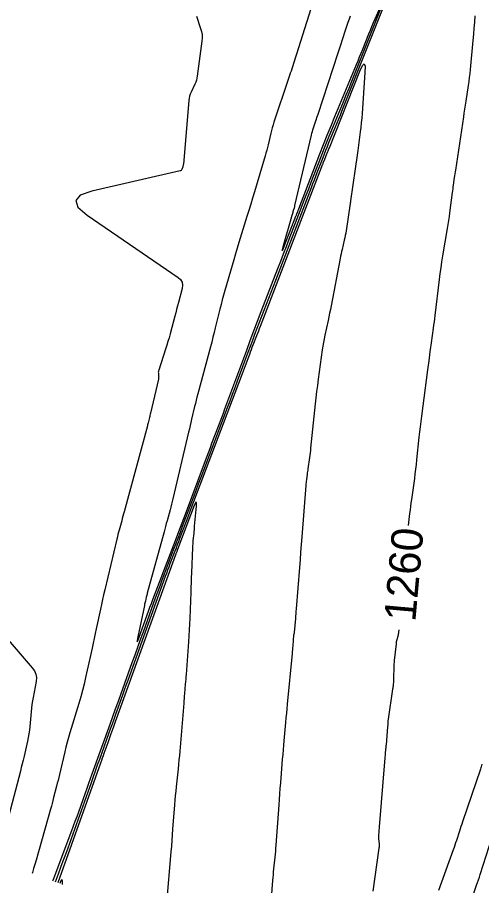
# Model space of a CAD drawing. Extents: x 658976 to 668721, y 639543 to 647196.
# Drawn here: x 661603.2 to 661691.9, y 641247 to 641412.7 of the extents above; entities that cross this region are included whole.
import ezdxf

# ---------------------------------------------------------------- set-up
doc = ezdxf.new("R2010")
doc.units = 0
for name, color, linetype in [('Ex_Contour Labels', 7, 'Continuous'), ('Ex_Major Contours', 7, 'Continuous'), ('Ex_Minor Contours', 7, 'Continuous')]:
    doc.layers.add(name, color=color, linetype=linetype)

msp = doc.modelspace()

# ---------------------------------------------------------------- linework, layer by layer
at = {"layer": 'Ex_Major Contours'}
for points in [[(661609.98, 641247.86), (661610.05, 641248.02), (661613.61, 641257.48), (661613.95, 641258.38), (661614.28, 641259.28), (661614.61, 641260.18), (661614.93, 641261.08), (661616.23, 641264.69), (661616.55, 641265.6), (661616.87, 641266.5), (661617.2, 641267.4), (661617.52, 641268.3), (661620.92, 641277.78), (661621.45, 641279.25), (661621.98, 641280.72), (661622.51, 641282.19), (661623.04, 641283.66), (661625.15, 641289.55), (661625.68, 641291.02), (661626.21, 641292.48), (661626.74, 641293.95), (661627.27, 641295.41), (661629.62, 641301.92), (661630.03, 641303.07), (661630.46, 641304.21), (661630.88, 641305.35), (661631.31, 641306.48), (661633.05, 641311.03), (661633.48, 641312.16), (661633.92, 641313.3), (661634.35, 641314.44), (661634.77, 641315.58), (661636.84, 641321.07), (661637.33, 641322.37), (661637.82, 641323.66), (661638.31, 641324.95), (661638.8, 641326.25), (661643.35, 641338.2), (661643.84, 641339.49), (661644.32, 641340.77), (661644.81, 641342.06), (661645.28, 641343.34), (661647.3, 641348.77), (661647.72, 641349.92), (661648.15, 641351.07), (661648.59, 641352.21), (661649.03, 641353.36), (661650.79, 641357.93), (661651.24, 641359.07), (661651.68, 641360.21), (661652.12, 641361.36), (661652.56, 641362.5), (661659.39, 641380.24), (661659.66, 641380.95), (661659.94, 641381.66), (661660.21, 641382.38), (661660.49, 641383.09), (661661.58, 641385.94), (661661.86, 641386.65), (661662.14, 641387.36), (661662.43, 641388.07), (661662.72, 641388.78), (661663.98, 641391.82), (661664.29, 641392.56), (661664.6, 641393.31), (661664.9, 641394.05), (661665.2, 641394.8), (661675.24, 641419.95)], [(661637.4, 641412.92), (661638.21, 641410.57), (661638.38, 641409.98), (661638.48, 641409.38), (661638.5, 641408.78), (661638.46, 641408.17), (661637.57, 641401.49), (661637.5, 641401.09), (661637.4, 641400.69), (661637.27, 641400.3), (661637.11, 641399.92), (661636.4, 641398.42), (661636.24, 641398.04), (661636.11, 641397.65), (661636.03, 641397.25), (661635.97, 641396.84), (661634.91, 641384.64), (661634.9, 641384.52), (661634.87, 641384.39), (661634.84, 641384.27), (661634.8, 641384.15), (661634.62, 641383.67), (661634.56, 641383.56), (661634.49, 641383.48), (661634.39, 641383.42), (661634.28, 641383.38), (661617.42, 641379.53), (661615.23, 641378.75), (661614.35, 641377.73), (661614.79, 641376.45), (661616.55, 641374.92), (661633.9, 641363.05), (661634.38, 641362.63), (661634.66, 641362.14), (661634.77, 641361.58), (661634.68, 641360.95), (661633.98, 641358.29), (661633.8, 641357.62), (661633.62, 641356.96), (661633.45, 641356.3), (661633.27, 641355.63), (661632.37, 641352.28), (661632.17, 641351.55), (661631.96, 641350.83), (661631.74, 641350.11), (661631.51, 641349.39), (661630.2, 641345.36), (661630.17, 641345.22), (661630.14, 641345.09), (661630.13, 641344.94), (661630.14, 641344.8), (661630.19, 641344.23), (661630.2, 641344.08), (661630.19, 641343.94), (661630.18, 641343.8), (661630.15, 641343.66), (661628.62, 641337.14), (661628.57, 641336.94), (661628.52, 641336.73), (661628.48, 641336.53), (661628.43, 641336.33), (661628.24, 641335.53), (661628.19, 641335.33), (661628.14, 641335.13), (661628.09, 641334.93), (661628.04, 641334.73), (661623.61, 641318.34), (661623.49, 641317.9), (661623.37, 641317.46), (661623.25, 641317.02), (661623.13, 641316.59), (661622.66, 641314.84), (661622.54, 641314.4), (661622.42, 641313.96), (661622.31, 641313.52), (661622.21, 641313.08), (661619.89, 641303.4), (661619.67, 641302.48), (661619.46, 641301.56), (661619.26, 641300.63), (661619.07, 641299.71), (661618.29, 641296.01), (661618.1, 641295.09), (661617.9, 641294.16), (661617.7, 641293.24), (661617.5, 641292.32), (661616.25, 641286.69), (661615.96, 641285.44), (661615.65, 641284.21), (661615.31, 641282.98), (661614.95, 641281.75), (661613.23, 641276.12), (661612.96, 641275.22), (661612.71, 641274.33), (661612.48, 641273.42), (661612.26, 641272.52), (661611.24, 641268.16), (661611.11, 641267.61), (661610.98, 641267.06), (661610.84, 641266.51), (661610.7, 641265.96), (661610.14, 641263.77), (661610, 641263.22), (661609.85, 641262.67), (661609.71, 641262.13), (661609.55, 641261.58), (661606.78, 641251.8), (661606.55, 641251.03), (661606.32, 641250.26), (661606.09, 641249.49), (661606.03, 641249.3)], [(661690.55, 641412.98), (661690.48, 641411.8), (661690.39, 641410.62), (661690.3, 641409.45), (661690.2, 641408.27), (661689.68, 641402.74), (661689.6, 641401.98), (661689.51, 641401.22), (661689.41, 641400.47), (661689.3, 641399.71), (661688.84, 641396.7), (661688.72, 641395.94), (661688.61, 641395.19), (661688.49, 641394.43), (661688.38, 641393.68), (661686.85, 641383.53), (661686.8, 641383.18), (661686.75, 641382.82), (661686.69, 641382.46), (661686.64, 641382.1), (661686.44, 641380.67), (661686.39, 641380.32), (661686.35, 641379.96), (661686.3, 641379.6), (661686.25, 641379.24), (661685.74, 641375.41), (661685.64, 641374.66), (661685.53, 641373.9), (661685.41, 641373.15), (661685.29, 641372.39), (661684.4, 641367.16), (661684.22, 641366.03), (661684.05, 641364.9), (661683.9, 641363.77), (661683.75, 641362.64), (661682.94, 641355.78), (661682.87, 641355.18), (661682.79, 641354.57), (661682.71, 641353.96), (661682.63, 641353.36), (661682.23, 641350.58), (661682.17, 641350.15), (661682.11, 641349.72), (661682.05, 641349.29), (661681.99, 641348.86), (661681.76, 641347.14), (661681.7, 641346.71), (661681.65, 641346.28), (661681.59, 641345.85), (661681.53, 641345.42), (661680.36, 641336.59), (661680.23, 641335.57), (661680.11, 641334.56), (661680, 641333.55), (661679.89, 641332.54), (661679.45, 641328.23), (661679.36, 641327.34), (661679.25, 641326.45), (661679.14, 641325.56), (661679.02, 641324.67), (661678.46, 641320.68), (661678.37, 641320.01), (661678.28, 641319.34), (661678.2, 641318.67), (661678.12, 641318), (661677.85, 641315.73)], [(661676.06, 641295.81), (661676.02, 641295.34), (661675.99, 641295.15), (661675.96, 641294.96), (661675.93, 641294.78), (661675.88, 641294.59), (661675.67, 641293.86), (661675.62, 641293.68), (661675.58, 641293.49), (661675.55, 641293.31), (661675.53, 641293.12), (661675.19, 641289.95), (661675.16, 641289.59), (661675.13, 641289.23), (661675.11, 641288.87), (661675.1, 641288.52), (661675.07, 641286.74), (661675.07, 641286.55), (661675.06, 641286.36), (661675.05, 641286.17), (661675.03, 641285.98), (661674.96, 641285.22), (661674.95, 641285.03), (661674.92, 641284.84), (661674.9, 641284.65), (661674.87, 641284.46), (661674.01, 641278.71), (661674, 641278.6), (661673.99, 641278.48), (661673.98, 641278.36), (661673.97, 641278.24), (661673.95, 641277.77), (661673.94, 641277.66), (661673.93, 641277.54), (661673.92, 641277.42), (661673.91, 641277.3), (661673.62, 641273.84), (661673.6, 641273.63), (661673.58, 641273.43), (661673.56, 641273.22), (661673.54, 641273.02), (661673.46, 641272.2), (661673.44, 641271.99), (661673.42, 641271.79), (661673.4, 641271.58), (661673.38, 641271.37), (661672.33, 641258.16), (661672.32, 641258.09), (661672.31, 641258.02), (661672.31, 641257.95), (661672.3, 641257.88), (661672.27, 641257.6), (661672.27, 641257.54), (661672.26, 641257.47), (661672.26, 641257.4), (661672.25, 641257.33), (661672.2, 641256.53), (661672.19, 641256.38), (661672.19, 641256.22), (661672.19, 641256.06), (661672.2, 641255.91), (661672.28, 641254.97), (661672.29, 641254.76), (661672.29, 641254.55), (661672.28, 641254.34), (661672.25, 641254.14), (661671.08, 641245.9)]]:
    msp.add_lwpolyline(points, dxfattribs=at)
at = {"layer": 'Ex_Minor Contours'}
for points in [[(661660.43, 641418.02), (661656.53, 641405.68), (661656.4, 641405.27), (661656.27, 641404.87), (661656.14, 641404.46), (661656, 641404.05), (661655.47, 641402.43), (661655.33, 641402.02), (661655.2, 641401.62), (661655.07, 641401.21), (661654.93, 641400.81), (661652.22, 641392.7), (661652.05, 641392.17), (661651.9, 641391.63), (661651.75, 641391.1), (661651.62, 641390.56), (661651.11, 641388.39), (661650.98, 641387.85), (661650.84, 641387.31), (661650.69, 641386.77), (661650.53, 641386.23), (661648.5, 641379.4), (661648.14, 641378.21), (661647.78, 641377.03), (661647.41, 641375.84), (661647.05, 641374.65), (661645.51, 641369.71), (661645.17, 641368.62), (661644.84, 641367.53), (661644.52, 641366.44), (661644.21, 641365.35), (661642.84, 641360.56), (661642.59, 641359.67), (661642.35, 641358.78), (661642.11, 641357.88), (661641.89, 641356.99), (661641, 641353.41), (661640.78, 641352.51), (661640.55, 641351.62), (661640.32, 641350.72), (661640.08, 641349.83), (661637.67, 641340.83), (661637.51, 641340.22), (661637.35, 641339.62), (661637.2, 641339.01), (661637.06, 641338.4), (661636.49, 641335.97), (661636.34, 641335.37), (661636.2, 641334.76), (661636.06, 641334.15), (661635.91, 641333.54), (661632.9, 641320.82), (661632.78, 641320.28), (661632.64, 641319.75), (661632.51, 641319.23), (661632.37, 641318.7), (661631.8, 641316.59), (661631.65, 641316.06), (661631.51, 641315.53), (661631.37, 641315), (661631.22, 641314.48), (661628.03, 641302.79), (661627.98, 641302.6), (661627.93, 641302.41), (661627.88, 641302.21), (661627.83, 641302.02), (661627.65, 641301.24), (661627.6, 641301.05), (661627.56, 641300.85), (661627.52, 641300.66), (661627.47, 641300.46), (661626.22, 641294.43), (661626.09, 641293.73), (661626.09, 641293.48), (661626.21, 641293.69), (661626.47, 641294.36), (661628.27, 641299.35), (661628.33, 641299.53), (661628.4, 641299.72), (661628.47, 641299.9), (661628.53, 641300.09), (661628.8, 641300.82), (661628.86, 641301), (661628.93, 641301.19), (661629, 641301.37), (661629.07, 641301.55), (661632.76, 641311.2), (661633.39, 641312.87), (661634.03, 641314.54), (661634.66, 641316.21), (661635.29, 641317.88), (661639.14, 641328.12), (661639.45, 641328.94), (661639.76, 641329.75), (661640.07, 641330.57), (661640.38, 641331.39), (661641.63, 641334.67), (661641.94, 641335.48), (661642.25, 641336.3), (661642.55, 641337.12), (661642.86, 641337.94), (661647.02, 641349.17), (661647.7, 641351.01), (661648.4, 641352.85), (661649.1, 641354.69), (661649.8, 641356.53), (661652.98, 641364.75), (661653.52, 641366.15), (661654.06, 641367.55), (661654.6, 641368.95), (661655.13, 641370.35), (661657.4, 641376.24), (661657.88, 641377.49), (661658.37, 641378.74), (661658.85, 641379.99), (661659.33, 641381.24), (661661.26, 641386.25), (661661.74, 641387.5), (661662.24, 641388.75), (661662.74, 641389.99), (661663.25, 641391.23), (661665.47, 641396.58), (661666.01, 641397.88), (661666.55, 641399.19), (661667.08, 641400.5), (661667.6, 641401.81), (661672.53, 641414.16)], [(661674.17, 641418.45), (661671.48, 641412.35), (661671.17, 641411.63), (661670.86, 641410.91), (661670.56, 641410.18), (661670.26, 641409.45), (661669.1, 641406.53), (661668.8, 641405.8), (661668.51, 641405.07), (661668.21, 641404.34), (661667.91, 641403.61), (661663.78, 641393.69), (661663.05, 641391.91), (661662.33, 641390.13), (661661.62, 641388.35), (661660.93, 641386.56), (661656.89, 641376.05), (661656.84, 641375.93), (661656.8, 641375.82), (661656.75, 641375.7), (661656.71, 641375.58), (661656.53, 641375.12), (661656.48, 641375), (661656.44, 641374.88), (661656.39, 641374.77), (661656.35, 641374.65), (661654.19, 641369.08), (661653.91, 641368.38), (661653.79, 641368.16), (661653.83, 641368.41), (661654.02, 641369.13), (661655.61, 641374.68), (661655.64, 641374.78), (661655.67, 641374.88), (661655.7, 641374.98), (661655.73, 641375.08), (661655.85, 641375.48), (661655.88, 641375.57), (661655.91, 641375.67), (661655.94, 641375.77), (661655.97, 641375.87), (661656.11, 641376.32), (661656.14, 641376.42), (661656.17, 641376.53), (661656.19, 641376.64), (661656.22, 641376.75), (661659.39, 641390.23), (661659.47, 641390.57), (661659.56, 641390.91), (661659.66, 641391.25), (661659.77, 641391.58), (661660.21, 641392.91), (661660.32, 641393.24), (661660.43, 641393.58), (661660.54, 641393.91), (661660.65, 641394.24), (661664.5, 641405.89), (661664.69, 641406.48), (661664.88, 641407.07), (661665.07, 641407.66), (661665.26, 641408.25), (661666.01, 641410.62), (661666.2, 641411.21), (661666.4, 641411.8), (661666.62, 641412.38), (661666.84, 641412.96)], [(661610.47, 641247.68), (661611.07, 641249.25), (661611.53, 641250.49), (661611.99, 641251.73), (661612.44, 641252.97), (661612.89, 641254.21), (661617.34, 641266.66), (661617.74, 641267.78), (661618.14, 641268.89), (661618.54, 641270.01), (661618.95, 641271.13), (661620.69, 641276), (661621.02, 641276.92), (661621.36, 641277.85), (661621.69, 641278.77), (661622.02, 641279.7), (661623.35, 641283.4), (661623.69, 641284.32), (661624.02, 641285.25), (661624.35, 641286.17), (661624.69, 641287.1), (661631.52, 641306.02), (661631.74, 641306.63), (661631.96, 641307.23), (661632.19, 641307.84), (661632.42, 641308.44), (661633.34, 641310.86), (661633.57, 641311.46), (661633.8, 641312.06), (661634.03, 641312.67), (661634.26, 641313.27), (661635.36, 641316.19), (661635.62, 641316.88), (661635.88, 641317.57), (661636.14, 641318.25), (661636.4, 641318.94), (661646.03, 641344.22), (661646.22, 641344.73), (661646.41, 641345.23), (661646.6, 641345.74), (661646.78, 641346.25), (661647.58, 641348.38), (661647.74, 641348.83), (661647.91, 641349.28), (661648.08, 641349.73), (661648.26, 641350.18), (661648.95, 641351.98), (661649.12, 641352.43), (661649.3, 641352.88), (661649.47, 641353.33), (661649.64, 641353.78), (661661.37, 641384.24), (661661.44, 641384.41), (661661.51, 641384.59), (661661.58, 641384.76), (661661.64, 641384.93), (661661.91, 641385.63), (661661.98, 641385.8), (661662.05, 641385.97), (661662.12, 641386.15), (661662.19, 641386.32), (661662.49, 641387.06), (661662.57, 641387.24), (661662.64, 641387.42), (661662.72, 641387.61), (661662.79, 641387.79), (661668.63, 641402.41), (661669.13, 641403.51), (661669.46, 641403.84), (661669.62, 641403.4), (661669.59, 641402.19), (661669.05, 641394.34), (661668.98, 641393.46), (661668.89, 641392.57), (661668.8, 641391.69), (661668.69, 641390.81), (661668.22, 641387.28), (661668.1, 641386.4), (661667.98, 641385.52), (661667.86, 641384.64), (661667.73, 641383.76), (661666.85, 641377.67), (661666.85, 641377.62), (661666.84, 641377.58), (661666.83, 641377.54), (661666.83, 641377.5), (661666.8, 641377.33), (661666.79, 641377.29), (661666.78, 641377.25), (661666.78, 641377.21), (661666.77, 641377.16), (661665.98, 641371.96), (661665.91, 641371.52), (661665.83, 641371.07), (661665.74, 641370.62), (661665.64, 641370.18), (661665.23, 641368.41), (661665.13, 641367.97), (661665.03, 641367.53), (661664.94, 641367.08), (661664.85, 641366.64), (661663.12, 641357.65), (661662.98, 641356.95), (661662.84, 641356.25), (661662.69, 641355.55), (661662.54, 641354.85), (661661.93, 641352.05), (661661.78, 641351.35), (661661.65, 641350.65), (661661.53, 641349.94), (661661.43, 641349.23), (661660.66, 641343.61), (661660.5, 641342.43), (661660.36, 641341.26), (661660.22, 641340.08), (661660.09, 641338.9), (661659.22, 641330.45), (661659.17, 641330.01), (661659.12, 641329.56), (661659.06, 641329.12), (661659, 641328.67), (661658.68, 641326.53), (661658.65, 641326.27), (661658.61, 641326.01), (661658.57, 641325.74), (661658.54, 641325.48), (661658.4, 641324.42), (661658.37, 641324.16), (661658.34, 641323.9), (661658.31, 641323.63), (661658.29, 641323.37), (661657.54, 641313.55), (661657.43, 641312.08), (661657.31, 641310.61), (661657.2, 641309.14), (661657.08, 641307.67), (661656.46, 641299.77), (661656.42, 641299.31), (661656.38, 641298.86), (661656.35, 641298.4), (661656.31, 641297.94), (661656.07, 641295.28), (661656.07, 641295.24), (661656.06, 641295.2), (661656.05, 641295.15), (661656.04, 641295.11), (661655.99, 641294.95), (661655.98, 641294.91), (661655.97, 641294.86), (661655.96, 641294.82), (661655.96, 641294.78), (661655.8, 641292.71), (661655.77, 641292.35), (661655.74, 641291.99), (661655.71, 641291.63), (661655.68, 641291.27), (661654.75, 641281.61), (661654.66, 641280.74), (661654.58, 641279.86), (661654.5, 641278.99), (661654.42, 641278.12), (661654.11, 641274.62), (661654.04, 641273.75), (661653.96, 641272.88), (661653.89, 641272), (661653.81, 641271.13), (661653.44, 641266.57), (661653.35, 641265.52), (661653.27, 641264.47), (661653.19, 641263.42), (661653.12, 641262.37), (661652.58, 641254.66), (661652.53, 641254.1), (661652.49, 641253.54), (661652.44, 641252.98), (661652.38, 641252.42), (661652.15, 641250.17), (661652.09, 641249.61), (661652.04, 641249.05), (661651.99, 641248.49), (661651.94, 641247.93), (661651.46, 641242.03)], [(661631.77, 641243.64), (661632.59, 641253.44), (661632.68, 641254.51), (661632.77, 641255.58), (661632.85, 641256.65), (661632.93, 641257.72), (661633.29, 641262.42), (661633.36, 641263.28), (661633.43, 641264.13), (661633.51, 641264.98), (661633.6, 641265.84), (661633.97, 641269.24), (661634.06, 641270.09), (661634.14, 641270.95), (661634.22, 641271.8), (661634.29, 641272.65), (661635.04, 641281.8), (661635.08, 641282.25), (661635.12, 641282.71), (661635.16, 641283.16), (661635.19, 641283.62), (661635.35, 641285.44), (661635.39, 641285.89), (661635.43, 641286.35), (661635.46, 641286.81), (661635.5, 641287.26), (661635.96, 641293.51), (661636.04, 641294.64), (661636.1, 641295.77), (661636.16, 641296.9), (661636.2, 641298.02), (661636.37, 641302.95), (661636.4, 641303.88), (661636.44, 641304.8), (661636.47, 641305.72), (661636.51, 641306.64), (661636.72, 641311.5), (661636.73, 641311.84), (661636.76, 641312.18), (661636.78, 641312.52), (661636.81, 641312.86), (661636.95, 641314.21), (661636.98, 641314.55), (661637.01, 641314.89), (661637.04, 641315.23), (661637.07, 641315.56), (661637.4, 641319.41), (661637.42, 641319.98), (661637.36, 641320.19), (661637.22, 641320.03), (661636.99, 641319.5), (661633.99, 641311.63), (661633.96, 641311.55), (661633.93, 641311.47), (661633.9, 641311.39), (661633.87, 641311.31), (661633.74, 641310.97), (661633.72, 641310.9), (661633.69, 641310.83), (661633.66, 641310.76), (661633.64, 641310.69), (661633.53, 641310.4), (661633.5, 641310.33), (661633.47, 641310.26), (661633.45, 641310.19), (661633.42, 641310.12), (661622.1, 641278.77), (661621.96, 641278.39), (661621.83, 641278.01), (661621.69, 641277.63), (661621.55, 641277.25), (661621.01, 641275.73), (661620.87, 641275.35), (661620.73, 641274.97), (661620.6, 641274.59), (661620.46, 641274.21), (661619.74, 641272.21), (661619.58, 641271.75), (661619.41, 641271.29), (661619.25, 641270.83), (661619.08, 641270.37), (661610.91, 641247.52)], [(661599.1, 641296.57), (661606.07, 641288.56), (661606.49, 641287.97), (661606.74, 641287.34), (661606.84, 641286.67), (661606.78, 641285.95), (661606.2, 641282.9), (661606.08, 641282.21), (661605.97, 641281.51), (661605.89, 641280.82), (661605.82, 641280.12), (661605.59, 641277.32), (661605.52, 641276.62), (661605.42, 641275.93), (661605.3, 641275.24), (661605.15, 641274.55), (661604.48, 641271.65), (661604.31, 641270.94), (661604.14, 641270.23), (661603.96, 641269.52), (661603.78, 641268.82), (661601.61, 641260.34)], [(661691.91, 641270.13), (661691.84, 641269.9), (661691.78, 641269.67), (661691.71, 641269.45), (661691.63, 641269.22), (661688.22, 641259.17), (661688.06, 641258.72), (661687.92, 641258.28), (661687.77, 641257.83), (661687.62, 641257.38), (661687.05, 641255.57), (661686.9, 641255.12), (661686.75, 641254.67), (661686.6, 641254.23), (661686.44, 641253.78), (661683.65, 641246.06)], [(661690.18, 641244.98), (661690.92, 641247.04), (661691.1, 641247.55), (661691.28, 641248.06), (661691.45, 641248.58), (661691.62, 641249.1), (661693.88, 641256.2)], [(661611.82, 641247.19), (661611.84, 641247.79), (661611.73, 641248.15), (661611.49, 641247.87), (661611.29, 641247.38)]]:
    msp.add_lwpolyline(points, dxfattribs=at)

# ---------------------------------------------------------------- texts
at = {"layer": 'Ex_Contour Labels'}
msp.add_text('1260', height=6, rotation=84.8606, dxfattribs=at).set_placement((661679.2, 641297.2))

doc.saveas('drawing.dxf')
